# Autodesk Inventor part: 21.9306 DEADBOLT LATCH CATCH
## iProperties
Created: 2012-07
Part Number: 21.9306 DEADBOLT LATCH CATCH
Document SubType Name: Modeling
Designer: Administrator
Density: 7.85 g/cm^3
Material: Cast Steel
Mass: 46.0262 g
Surface Area: 40.7248 cm^2
Volume: 5.86321 cm^3
Author: Administrator
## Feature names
1. Base1
